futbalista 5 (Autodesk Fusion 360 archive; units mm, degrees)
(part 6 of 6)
part number: 8 PIN HEADER, IC, BTS7960 43A HIGH POWER H BRIDGE MODULE
part number: ALUMINUM ELECTROLYTIC CAPACITOR, 330 uF, BTS7960 43A HIGH POWER H BRIDGE MODULE

design "arduino nano strong"
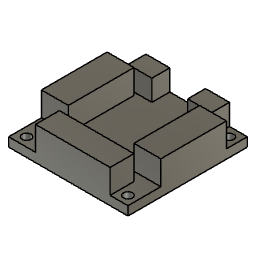
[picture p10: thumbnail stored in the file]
base_feature "Base Feature"

design "Battery 18650"
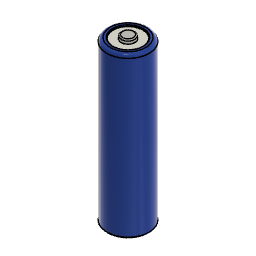
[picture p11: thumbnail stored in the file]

design "rpiCameraMAssembly"
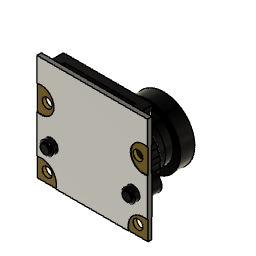
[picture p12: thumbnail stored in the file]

design "Raspberry Pi 4 Model B"
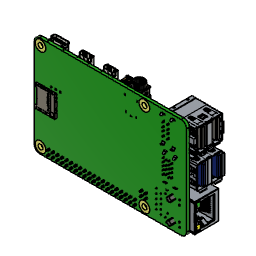
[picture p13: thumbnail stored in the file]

design "stlpik"
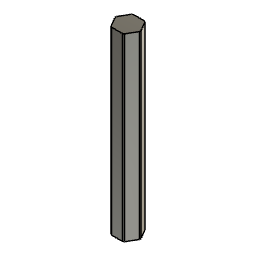
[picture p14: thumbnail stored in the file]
sketch "Sketch1" plane through (0, 0, 0) normal (0, 0, 1) x axis (1, 0, 0)
  line L1 (-1.5025, 3.05) -> (1.5025, 3.05)
  line L2 (-3.3926, 0.2238) -> (-1.8901, 2.8262)
  line L3 (-1.8901, -2.8262) -> (-3.3926, -0.2238)
  line L4 (1.5025, -3.05) -> (-1.5025, -3.05)
  line L5 (3.3926, -0.2238) -> (1.8901, -2.8262)
  line L6 (1.8901, 2.8262) -> (3.3926, 0.2238)
  circle C1 centre (0, 0) radius 3.4
  point P1 (0, 0)
  point P2 (0, 0)
  point P3 (1.5025, 3.05)
  point P4 (-1.5025, 3.05)
  coincident P1 P2
  coincident C1 P3
  coincident C1 P4
  dimension "d1" diameter C1 = 6.8
  dimension "d4" C-Pattern1-Angle = 360
extrude "Extrude1" new body sketch "Sketch1" along normal blind 50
